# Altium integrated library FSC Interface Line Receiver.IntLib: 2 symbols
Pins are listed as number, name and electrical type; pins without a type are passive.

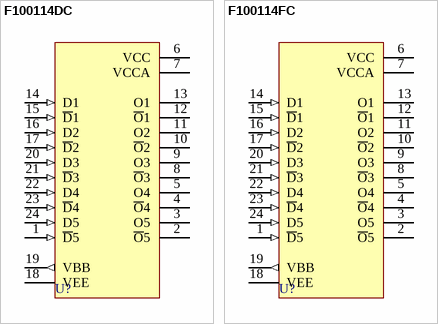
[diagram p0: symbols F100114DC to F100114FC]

## F100114DC
designator U?
Quint Differential Line Receiver
footprint 6Y (DIP; 24 Leads; Row Spacing 10.16 mm; Pitch 2.54 mm)
3D model 6Y (DIP; 24 Leads; Row Spacing 10.16 mm; Pitch 2.54 mm)
pins: 1 ~{D}5 (in), 2 ~{O}5 (oe), 3 O5 (oe), 4 ~{O}4 (oe), 5 O4 (oe), 6 VCC (power), 7 VCCA (power), 8 ~{O}3 (oe), 9 O3 (oe), 10 ~{O}2 (oe), 11 O2 (oe), 12 ~{O}1 (oe), 13 O1 (oe), 14 D1 (in), 15 ~{D}1 (in), 16 D2 (in), 17 ~{D}2 (in), 18 VEE (power), 19 VBB (out), 20 D3 (in), 21 ~{D}3 (in), 22 D4 (in), 23 ~{D}4 (in), 24 D5 (in)

## F100114FC
designator U?
Quint Differential Line Receiver
footprint 4V_N (CQFP, 24-Leads, Body 10x10mm; Pitch 1.27mm, Gullwing Leadform, IPC Medium Density)
footprint 4V_L (CQFP, 24-Leads, Body 10x10mm; Pitch 1.27mm, Gullwing Leadform, IPC High Density)
footprint 4V_M (CQFP, 24-Leads, Body 10x10mm; Pitch 1.27mm, Gullwing Leadform, IPC Low Density)
3D model F100114-4V (100-Pin Quad Cerpak 1.27 mm Pitch)
pins: 1 ~{D}5 (in), 2 ~{O}5 (oe), 3 O5 (oe), 4 ~{O}4 (oe), 5 O4 (oe), 6 VCC (power), 7 VCCA (power), 8 ~{O}3 (oe), 9 O3 (oe), 10 ~{O}2 (oe), 11 O2 (oe), 12 ~{O}1 (oe), 13 O1 (oe), 14 D1 (in), 15 ~{D}1 (in), 16 D2 (in), 17 ~{D}2 (in), 18 VEE (power), 19 VBB (out), 20 D3 (in), 21 ~{D}3 (in), 22 D4 (in), 23 ~{D}4 (in), 24 D5 (in)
